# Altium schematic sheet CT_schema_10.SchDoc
size 274 x 160 mm
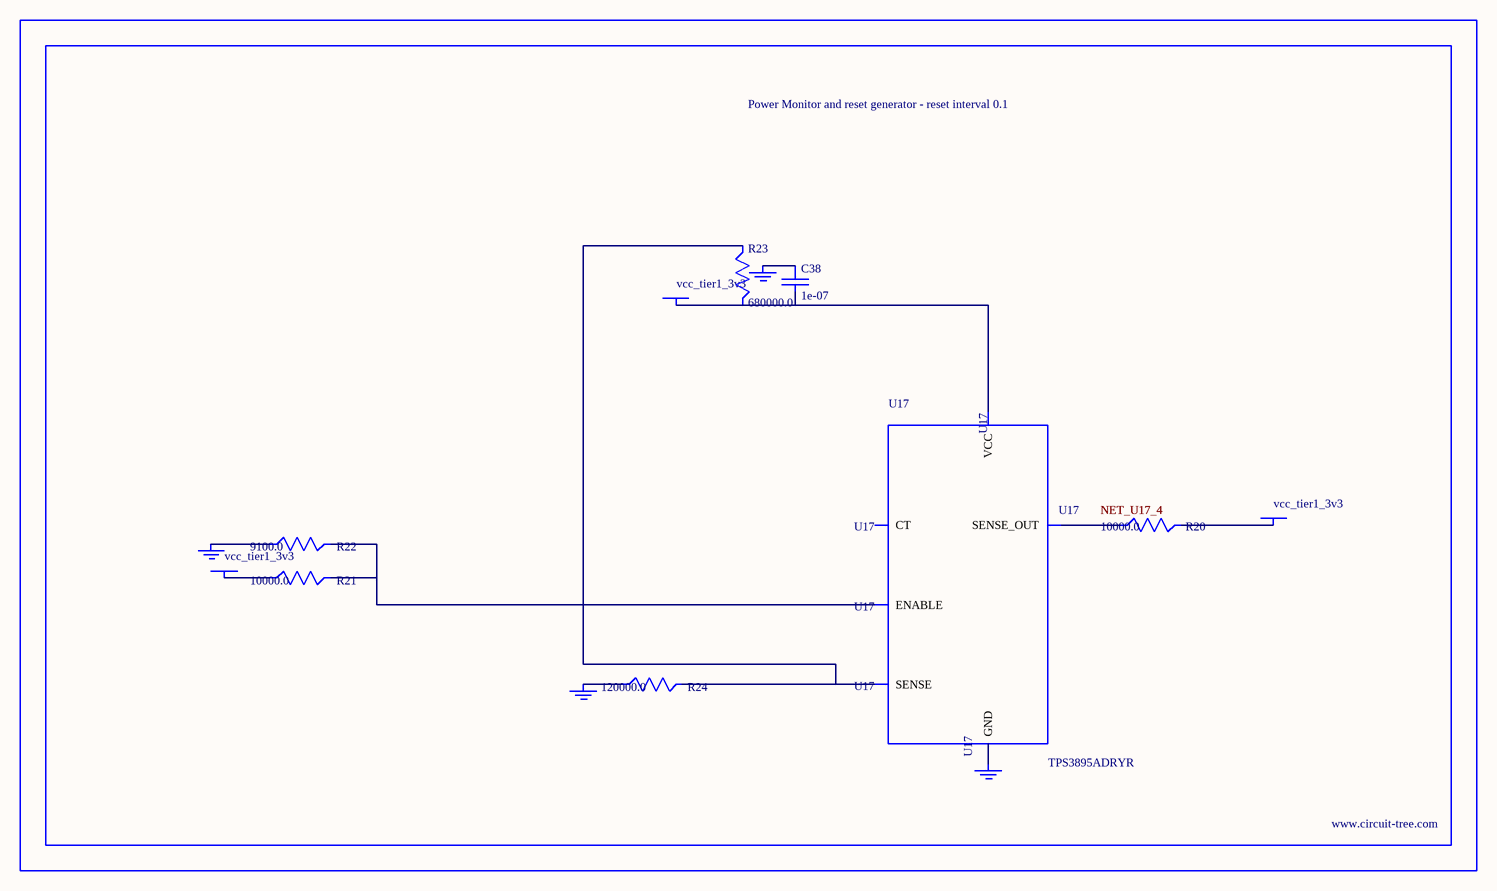
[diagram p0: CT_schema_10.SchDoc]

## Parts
BORDER9  (no value)
C38  1e-07  [C0402]
GND_INSTANCE_9_0  (no value)
GND_INSTANCE_9_1  (no value)
GND_INSTANCE_9_2  (no value)
GND_INSTANCE_9_3  (no value)
POWER_INSTANCE_9_0  vcc_tier1_3v3
POWER_INSTANCE_9_1  vcc_tier1_3v3
POWER_INSTANCE_9_2  vcc_tier1_3v3
R20  10000.0  [R0603]
R21  10000.0  [R0603]
R22  9100.0  [R0603]
R23  680000.0  [R0603]
R24  120000.0  [R0603]
U17  TPS3895ADRYR  [SON-6]

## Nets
NetC38_1: C38.1 GND_INSTANCE_9_2.0(GND)
NetC38_2: C38.2 POWER_INSTANCE_9_2.0(PWR) R23.2 U17.6(VCC)
NetGND_INSTANCE_9_0_0: GND_INSTANCE_9_0.0(GND) R22.1
NetGND_INSTANCE_9_1_0: GND_INSTANCE_9_1.0(GND) R24.1
NetGND_INSTANCE_9_3_0: GND_INSTANCE_9_3.0(GND) U17.2(GND)
NetPOWER_INSTANCE_9_0_0: POWER_INSTANCE_9_0.0(PWR) R21.1
NetPOWER_INSTANCE_9_1_0: POWER_INSTANCE_9_1.0(PWR) R20.2
NetR20_1: R20.1 U17.4(SENSE_OUT)
NetR21_2: R21.2 R22.2 U17.1(ENABLE)
NetR23_1: R23.1 R24.2 U17.3(SENSE)

Not connected (* = marked no-connect by the designer): U17 5(CT)

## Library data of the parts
BORDER9 = BORDER_PAGE9
C38 = C0402C104K3RACTU
GND_INSTANCE_9_0-GND_INSTANCE_9_3 = GND
POWER_INSTANCE_9_0-POWER_INSTANCE_9_2 = PWR
R20 R21 = RC0603JR-0710KL
R22 = RC0603JR-079K1L
R23 = RC0603JR-07680KL
R24 = RC0603JR-07120KL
